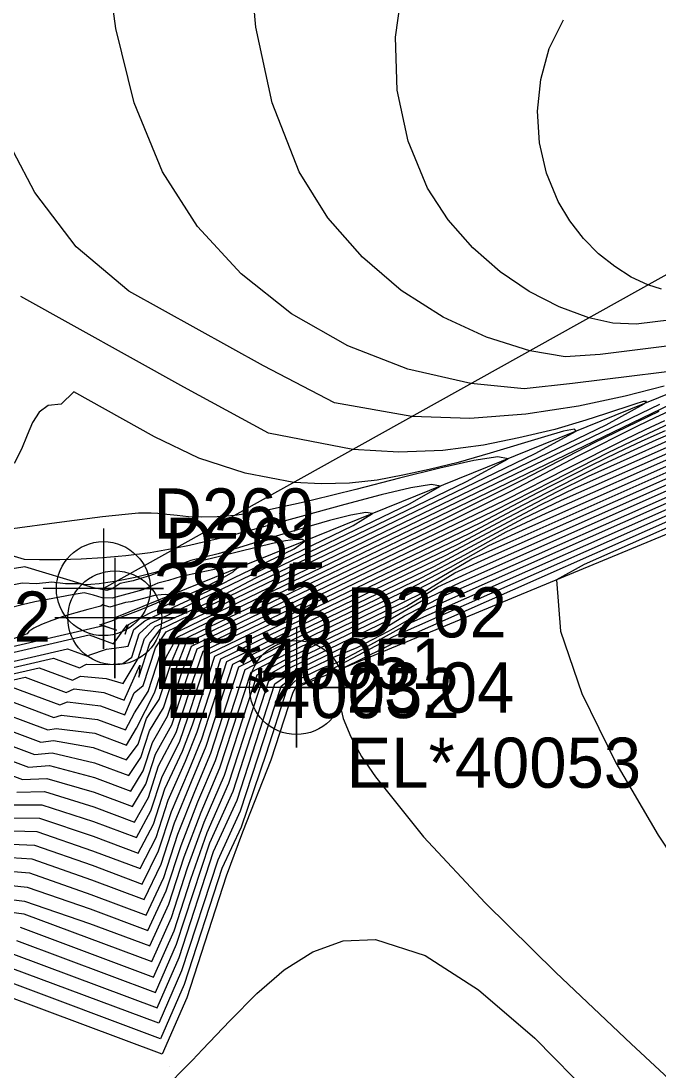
# Model space of a CAD drawing. Extents: x 2356077 to 2359823, y 225951 to 227822.
# Drawn here: x 2356615.2 to 2356647.1, y 227137.3 to 227189.6 of the extents above; entities that cross this region are included whole.
import ezdxf

# ---------------------------------------------------------------- set-up
doc = ezdxf.new("R2010")
doc.units = 0
for name, color, linetype in [('DTM Contours Major', 7, 'Continuous'), ('DTM Contours Minor', 7, 'Continuous'), ('Exist DTM Breakline', 7, 'Continuous'), ('Exist DTM Breakline Cogo Comment', 7, 'Continuous'), ('Exist DTM Breakline Cogo Elevation', 7, 'Continuous'), ('Exist DTM Breakline Cogo Number', 7, 'Continuous'), ('Exist DTM Breakline Cogo Point CELL', 7, 'Continuous'), ('PH Exist DTM Point', 7, 'Continuous')]:
    doc.layers.add(name, color=color, linetype=linetype)

msp = doc.modelspace()

# ---------------------------------------------------------------- linework, layer by layer
at = {"layer": 'DTM Contours Major'}
for points in [[(2356650.01, 227172.448), (2356642.738, 227171.549), (2356640.339, 227171.28), (2356637.674, 227171.536), (2356634.535, 227172.259), (2356631.531, 227173.429), (2356628.734, 227175.021), (2356626.215, 227177.013), (2356624.045, 227179.379), (2356622.295, 227182.097), (2356620.877, 227185.54), (2356619.972, 227189.251), (2356619.463, 227193.083)], [(2356615.023, 227143.755), (2356621.944, 227141.169), (2356622.999, 227143.575), (2356624.65, 227148.638), (2356625.814, 227151.21), (2356627.607, 227156.72), (2356628.683, 227157.379), (2356633.573, 227159.741), (2356635.194, 227160.69), (2356637.173, 227161.639), (2356649.972, 227167.313), (2356650.439, 227167.465), (2356651.114, 227167.675), (2356652.444, 227168.073), (2356653.739, 227168.444), (2356655.677, 227168.977), (2356656.136, 227169.085), (2356661.39, 227170.295), (2356670.074, 227172.299), (2356673.007, 227172.997), (2356680.252, 227175.044)], [(2356678.093, 227172.544), (2356655.561, 227167.344), (2356655.084, 227167.243), (2356654.826, 227167.194), (2356654.557, 227167.153), (2356654.09, 227166.995), (2356653.759, 227166.903), (2356652.029, 227166.502), (2356650.908, 227166.251), (2356650.707, 227166.131), (2356650.549, 227166.024), (2356634.344, 227158.84), (2356631.306, 227157.344), (2356631.098, 227156.541), (2356631.103, 227155.705), (2356631.304, 227154.831), (2356631.684, 227153.913), (2356632.227, 227152.943), (2356632.915, 227151.918), (2356635.318, 227148.938), (2356638.393, 227145.645), (2356641.918, 227142.16), (2356645.672, 227138.604), (2356649.432, 227135.1)], [(2356612.679, 227154.982), (2356616.238, 227153.652), (2356616.87, 227153.732), (2356618.841, 227153.387), (2356620.503, 227152.766), (2356621.082, 227153.556), (2356621.497, 227154.831), (2356622.136, 227155.779), (2356622.744, 227157.647), (2356623.193, 227158.705), (2356650.047, 227171.678)], [(2356614.748, 227150.522), (2356616.285, 227150.532), (2356618.86, 227149.694), (2356620.997, 227148.895), (2356621.719, 227150.223), (2356622.263, 227151.895), (2356623.161, 227153.703), (2356623.563, 227154.875), (2356624.079, 227156.459), (2356624.612, 227158.064), (2356638.204, 227164.63), (2356641.014, 227166.101), (2356643.681, 227167.465), (2356644.993, 227168.104), (2356646.222, 227168.682), (2356647.377, 227169.203)], [(2356613.461, 227147.317), (2356615.666, 227147.141), (2356618.725, 227146.058), (2356621.475, 227145.03), (2356622.36, 227146.9), (2356623.064, 227149.066), (2356623.906, 227151.189), (2356624.707, 227153.1), (2356626.112, 227157.418), (2356628.369, 227158.553), (2356635.23, 227161.868), (2356637.37, 227163.004), (2356639.43, 227164.146), (2356641.427, 227165.07), (2356648.56, 227168.232)], [(2356612.588, 227156.551), (2356616.155, 227157.369), (2356617.818, 227156.748), (2356618.207, 227156.938), (2356619.49, 227156.831), (2356620.343, 227156.575), (2356621.082, 227157.832), (2356621.404, 227158.82), (2356621.926, 227159.419), (2356624.84, 227160.735), (2356626.951, 227161.847), (2356634.606, 227165.545), (2356636.157, 227166.422), (2356635.718, 227166.507), (2356634.686, 227166.345), (2356633.196, 227165.994), (2356631.383, 227165.512), (2356627.329, 227164.392), (2356625.806, 227163.986), (2356625.066, 227163.799), (2356624.344, 227163.624), (2356623.64, 227163.465), (2356622.957, 227163.324), (2356621.675, 227163.101), (2356620.468, 227162.944), (2356619.325, 227162.841), (2356618.234, 227162.78), (2356617.184, 227162.752), (2356616.163, 227162.743), (2356615.412, 227162.757), (2356613.57, 227163.308)]]:
    msp.add_lwpolyline(points, dxfattribs=at)
at = {"layer": 'DTM Contours Minor'}
for points in [[(2356650.746, 227173.818), (2356644.113, 227172.997), (2356642.382, 227172.871), (2356640.617, 227173.179), (2356638.45, 227173.85), (2356636.287, 227174.854), (2356634.201, 227176.186), (2356632.263, 227177.841), (2356630.544, 227179.814), (2356629.115, 227182.1), (2356627.758, 227185.545), (2356626.949, 227189.324), (2356626.609, 227193.239)], [(2356651.2, 227175.152), (2356645.918, 227174.499), (2356644.746, 227174.546), (2356643.56, 227174.821), (2356642.083, 227175.362), (2356640.589, 227176.13), (2356639.132, 227177.116), (2356637.765, 227178.31), (2356636.542, 227179.704), (2356635.517, 227181.288), (2356634.541, 227183.63), (2356634.005, 227186.176), (2356633.915, 227188.817), (2356634.278, 227191.444)], [(2356647.179, 227176.242), (2356646.503, 227176.464), (2356645.675, 227176.854), (2356644.845, 227177.375), (2356644.04, 227178.02), (2356643.285, 227178.781), (2356642.605, 227179.651), (2356642.025, 227180.621), (2356641.449, 227182.033), (2356641.104, 227183.554), (2356641.003, 227185.132), (2356641.158, 227186.715), (2356641.582, 227188.252), (2356642.29, 227189.691)], [(2356647.309, 227171.404), (2356645.367, 227170.904), (2356643.037, 227170.406), (2356640.42, 227170.008), (2356637.617, 227169.805), (2356634.73, 227169.894), (2356630.881, 227170.584), (2356627.328, 227172.433), (2356620.626, 227176.156), (2356617.986, 227178.361), (2356615.934, 227181.068), (2356614.844, 227183.13)], [(2356612.706, 227145.45), (2356615.389, 227145.093), (2356621.766, 227142.71), (2356622.745, 227144.909), (2356623.549, 227147.38), (2356624.382, 227149.665), (2356625.382, 227152), (2356627.012, 227157.009), (2356628.556, 227157.848), (2356633.396, 227160.186), (2356635.255, 227161.105), (2356636.869, 227162.097), (2356638.918, 227163.03), (2356649.686, 227167.804), (2356650.547, 227168.087), (2356651.717, 227168.458), (2356652.869, 227168.806), (2356654.199, 227169.19), (2356655.566, 227169.57), (2356656.236, 227169.749), (2356668.347, 227172.543), (2356670.934, 227173.167), (2356679.732, 227175.653)], [(2356614.059, 227155.941), (2356616.874, 227154.889), (2356617.264, 227155.004), (2356619.059, 227154.78), (2356620.449, 227154.261), (2356620.901, 227155.116), (2356621.58, 227156.188), (2356622.213, 227158.132), (2356622.755, 227159.024), (2356644.417, 227169.489), (2356646.31, 227170.53), (2356646.433, 227170.654), (2356646.269, 227170.641), (2356645.851, 227170.517), (2356644.388, 227170.027), (2356643.408, 227169.708), (2356641.859, 227169.256), (2356640.059, 227168.836), (2356638.3, 227168.46), (2356636.269, 227168.207), (2356634.087, 227168.122), (2356631.787, 227168.251), (2356627.585, 227169.066), (2356623.358, 227171.361), (2356615.232, 227175.876)], [(2356615.208, 227144.423), (2356621.856, 227141.939), (2356622.872, 227144.242), (2356623.709, 227146.814), (2356624.519, 227149.152), (2356625.601, 227151.614), (2356627.31, 227156.867), (2356628.619, 227157.613), (2356634.47, 227160.439), (2356636.028, 227161.4), (2356638.05, 227162.337), (2356649.819, 227167.554), (2356651.123, 227167.97), (2356652.366, 227168.349), (2356653.632, 227168.717), (2356654.95, 227169.087), (2356655.626, 227169.272), (2356656.207, 227169.422), (2356669.203, 227172.42), (2356671.967, 227173.081), (2356680.063, 227175.368)], [(2356614.868, 227143.076), (2356622.032, 227140.399), (2356623.127, 227142.908), (2356624.847, 227148.194), (2356626.014, 227150.766), (2356627.902, 227156.568), (2356628.748, 227157.145), (2356631.525, 227158.486), (2356632.933, 227159.081), (2356634.367, 227159.954), (2356636.294, 227160.94), (2356650.1, 227167.061), (2356650.393, 227167.165), (2356651.114, 227167.385), (2356652.537, 227167.803), (2356653.857, 227168.175), (2356655.096, 227168.514), (2356655.631, 227168.649), (2356656.369, 227168.815), (2356670.939, 227172.178), (2356674.04, 227172.911), (2356680.422, 227174.714)], [(2356680.521, 227174.363), (2356675.065, 227172.822), (2356671.803, 227172.056), (2356656.211, 227168.458), (2356655.553, 227168.313), (2356655.122, 227168.214), (2356654.576, 227168.073), (2356652.646, 227167.543), (2356651.887, 227167.327), (2356651.125, 227167.105), (2356650.408, 227166.888), (2356650.29, 227166.829), (2356650.219, 227166.804), (2356635.418, 227160.243), (2356633.542, 227159.175), (2356631.986, 227158.354), (2356630.892, 227157.915), (2356628.813, 227156.911), (2356628.195, 227156.411), (2356626.178, 227150.214), (2356625.052, 227147.769), (2356623.253, 227142.239), (2356622.118, 227139.629), (2356614.702, 227142.401)], [(2356678.704, 227172.364), (2356654.663, 227166.815), (2356654.556, 227166.801), (2356654.458, 227166.798), (2356654.374, 227166.815), (2356654.131, 227166.69), (2356653.89, 227166.624), (2356652.783, 227166.365), (2356651.253, 227166.013), (2356650.921, 227165.88), (2356643.322, 227162.511), (2356641.94, 227161.75), (2356642.15, 227159.196), (2356643.204, 227156.086), (2356644.896, 227152.624), (2356647.018, 227149.017), (2356649.365, 227145.471), (2356651.729, 227142.191), (2356653.059, 227140.45), (2356654.329, 227138.852), (2356655.548, 227137.372), (2356656.722, 227135.988)], [(2356614.756, 227156.417), (2356617.177, 227155.512), (2356617.561, 227155.665), (2356619.21, 227155.461), (2356620.415, 227155.011), (2356620.881, 227156.112), (2356621.33, 227156.477), (2356621.943, 227158.362), (2356622.479, 227159.156), (2356640.884, 227168.047), (2356642.926, 227169.161), (2356642.843, 227169.265), (2356642.291, 227169.158), (2356641.352, 227168.889), (2356638.644, 227168.062), (2356637.038, 227167.603), (2356635.587, 227167.258), (2356634.286, 227166.969), (2356633.002, 227166.73), (2356631.619, 227166.579), (2356630.23, 227166.531), (2356628.844, 227166.609), (2356626.427, 227167.068), (2356624.11, 227167.818), (2356621.906, 227168.89), (2356617.881, 227171.126), (2356617.247, 227170.521), (2356616.598, 227170.44), (2356616.146, 227170.114), (2356615.821, 227169.603), (2356615.551, 227168.967), (2356615.267, 227168.266), (2356614.896, 227167.558)], [(2356613.361, 227155.464), (2356616.574, 227154.263), (2356616.988, 227154.334), (2356618.923, 227154.094), (2356620.496, 227153.506), (2356620.997, 227154.352), (2356621.898, 227156.107), (2356622.482, 227157.9), (2356623.029, 227158.891), (2356647.104, 227170.521)], [(2356611.299, 227154.023), (2356615.613, 227152.411), (2356616.669, 227152.487), (2356618.907, 227151.888), (2356620.711, 227151.214), (2356621.337, 227152.224), (2356621.796, 227153.634), (2356622.553, 227154.945), (2356623.278, 227157.171), (2356623.746, 227158.442), (2356636.096, 227164.408), (2356639.692, 227166.183), (2356643.017, 227167.941), (2356646.007, 227169.436), (2356646.892, 227169.858), (2356647.727, 227170.246)], [(2356611.99, 227154.502), (2356615.919, 227153.034), (2356616.79, 227153.12), (2356618.9, 227152.627), (2356620.611, 227151.988), (2356621.21, 227152.89), (2356621.642, 227154.22), (2356622.348, 227155.371), (2356623.01, 227157.408), (2356623.461, 227158.57), (2356636.479, 227164.858), (2356640.275, 227166.751), (2356643.845, 227168.599), (2356647.067, 227170.165)], [(2356610.608, 227153.544), (2356615.313, 227151.786), (2356616.535, 227151.844), (2356618.895, 227151.155), (2356620.806, 227150.441), (2356621.465, 227151.556), (2356621.951, 227153.05), (2356622.759, 227154.52), (2356623.545, 227156.935), (2356624.033, 227158.315), (2356639.408, 227165.743), (2356642.482, 227167.301), (2356645.35, 227168.747), (2356646.382, 227169.247), (2356647.346, 227169.702)], [(2356614.479, 227149.886), (2356616.161, 227149.865), (2356618.837, 227148.965), (2356621.092, 227148.122), (2356621.847, 227149.558), (2356622.422, 227151.324), (2356623.3, 227153.201), (2356623.793, 227154.524), (2356624.905, 227157.939), (2356637.614, 227164.08), (2356640.282, 227165.486), (2356642.841, 227166.809), (2356644.277, 227167.515), (2356645.632, 227168.153), (2356646.909, 227168.728), (2356648.115, 227169.245)], [(2356615.026, 227151.156), (2356616.409, 227151.192), (2356618.879, 227150.424), (2356620.902, 227149.668), (2356621.592, 227150.889), (2356622.106, 227152.469), (2356622.977, 227154.13), (2356623.812, 227156.697), (2356624.321, 227158.189), (2356638.817, 227165.192), (2356641.759, 227166.695), (2356644.527, 227168.1), (2356645.704, 227168.672), (2356646.803, 227169.19), (2356647.831, 227169.658)], [(2356614.217, 227149.247), (2356616.037, 227149.192), (2356618.811, 227148.237), (2356621.188, 227147.349), (2356621.975, 227148.893), (2356622.582, 227150.757), (2356623.445, 227152.698), (2356624.023, 227154.17), (2356625.207, 227157.811), (2356628.185, 227159.26), (2356637.022, 227163.529), (2356639.55, 227164.869), (2356641.994, 227166.15), (2356643.547, 227166.919), (2356645.136, 227167.641), (2356647.814, 227168.828)], [(2356613.711, 227147.961), (2356615.79, 227147.828), (2356618.755, 227146.784), (2356621.379, 227145.803), (2356622.231, 227147.564), (2356622.903, 227149.628), (2356623.749, 227151.691), (2356624.48, 227153.459), (2356625.811, 227157.55), (2356628.307, 227158.788), (2356635.831, 227162.423), (2356638.092, 227163.628), (2356640.286, 227164.818), (2356642.193, 227165.718), (2356648.655, 227168.583)], [(2356613.962, 227148.605), (2356615.913, 227148.513), (2356618.784, 227147.51), (2356621.284, 227146.576), (2356622.103, 227148.228), (2356622.742, 227150.192), (2356623.595, 227152.195), (2356624.252, 227153.816), (2356625.509, 227157.681), (2356628.245, 227159.024), (2356636.428, 227162.977), (2356641.142, 227165.485), (2356642.884, 227166.333), (2356647.581, 227168.416)], [(2356612.013, 227156.115), (2356615.454, 227156.894), (2356617.492, 227156.132), (2356617.899, 227156.311), (2356619.377, 227156.136), (2356620.394, 227155.756), (2356621.163, 227157.502), (2356621.12, 227156.89), (2356621.673, 227158.589), (2356622.184, 227159.279), (2356637.461, 227166.659), (2356639.541, 227167.791), (2356639.012, 227167.883), (2356637.816, 227167.702), (2356636.124, 227167.323), (2356634.107, 227166.818), (2356631.937, 227166.262), (2356629.784, 227165.728), (2356629.058, 227165.558), (2356628.359, 227165.403), (2356627.691, 227165.263), (2356627.056, 227165.143), (2356626.458, 227165.043), (2356625.9, 227164.966), (2356625.019, 227164.889), (2356624.257, 227164.874), (2356623.597, 227164.901), (2356623.022, 227164.952), (2356622.515, 227165.011), (2356622.059, 227165.058), (2356621.732, 227165.077), (2356621.414, 227165.08), (2356621.098, 227165.069), (2356620.772, 227165.047), (2356620.428, 227165.014), (2356619.313, 227164.886), (2356617.531, 227164.661), (2356614.319, 227164.234)], [(2356612.971, 227146.026), (2356615.419, 227145.718), (2356618.652, 227144.611), (2356621.662, 227143.486), (2356622.616, 227145.57), (2356623.386, 227147.939), (2356624.225, 227150.16), (2356625.159, 227152.371), (2356626.713, 227157.148), (2356628.493, 227158.083), (2356634.015, 227160.75), (2356635.951, 227161.748), (2356637.72, 227162.791), (2356639.777, 227163.72), (2356649.508, 227168.034)], [(2356613.223, 227146.669), (2356615.546, 227146.426), (2356618.689, 227145.334), (2356621.569, 227144.258), (2356622.488, 227146.235), (2356623.225, 227148.502), (2356624.067, 227150.674), (2356624.934, 227152.738), (2356626.413, 227157.284), (2356628.431, 227158.318), (2356634.625, 227161.31), (2356636.656, 227162.378), (2356638.573, 227163.471), (2356640.616, 227164.401), (2356648.446, 227167.872)], [(2356650.53, 227166.326), (2356633.803, 227158.909), (2356630.274, 227157.048), (2356629.933, 227156.88), (2356629.417, 227156.612), (2356629.16, 227156.548), (2356628.955, 227156.449), (2356628.793, 227156.132), (2356627.692, 227152.75), (2356626.291, 227149.163), (2356625.479, 227146.965), (2356623.506, 227140.899), (2356622.279, 227138.095), (2356614.362, 227141.053)], [(2356650.33, 227166.545), (2356634.559, 227159.553), (2356631.889, 227158.073), (2356630.989, 227157.617), (2356630.254, 227157.342), (2356628.881, 227156.679), (2356628.488, 227156.253), (2356627.461, 227153.096), (2356626.225, 227149.417), (2356625.263, 227147.357), (2356623.38, 227141.569), (2356622.201, 227138.861), (2356614.537, 227141.725)], [(2356595.171, 227152.821), (2356616.86, 227157.843), (2356618.162, 227157.356), (2356618.512, 227157.538), (2356619.594, 227157.529), (2356620.323, 227157.572), (2356620.761, 227157.901), (2356621.135, 227159.052), (2356621.692, 227159.572), (2356631.8, 227164.455), (2356632.773, 227165.052), (2356632.436, 227165.101), (2356631.693, 227164.975), (2356630.626, 227164.708), (2356629.317, 227164.335), (2356627.847, 227163.89), (2356626.298, 227163.409), (2356625.068, 227163.05), (2356623.705, 227162.711), (2356622.843, 227162.404), (2356621.928, 227162.109), (2356620.937, 227161.868), (2356620.014, 227161.682), (2356619.565, 227161.611), (2356619.134, 227161.556), (2356618.72, 227161.516), (2356618.409, 227161.501), (2356615.425, 227162.392), (2356614.309, 227162.222)], [(2356598.231, 227153.833), (2356617.56, 227158.31), (2356617.93, 227158.18), (2356618.556, 227157.946), (2356618.682, 227158.016), (2356619.51, 227158.297), (2356620.245, 227158.389), (2356620.592, 227158.44), (2356620.865, 227159.279), (2356621.413, 227159.702), (2356622.879, 227160.411), (2356624.555, 227161.185), (2356625.854, 227161.848), (2356628.864, 227163.302), (2356629.388, 227163.682), (2356629.265, 227163.77), (2356628.931, 227163.769), (2356628.423, 227163.694), (2356627.776, 227163.561), (2356627.028, 227163.386), (2356624.129, 227162.663), (2356623.42, 227162.494), (2356622.707, 227162.331), (2356621.649, 227161.955), (2356621.206, 227161.813), (2356620.832, 227161.707), (2356620.498, 227161.626), (2356620.185, 227161.564), (2356619.781, 227161.295), (2356619.522, 227161.225), (2356618.849, 227161.355), (2356618.184, 227161.554), (2356617.462, 227161.547), (2356616.781, 227161.626), (2356616.022, 227161.547), (2356615.297, 227161.583), (2356613.054, 227161.143)], [(2356618.635, 227159.008), (2356619.847, 227158.555), (2356620.532, 227159.505), (2356620.444, 227159.045), (2356620.602, 227159.53), (2356621.648, 227160.081), (2356623.408, 227160.931), (2356624.503, 227161.441), (2356625.279, 227161.835), (2356625.822, 227162.143), (2356626.004, 227162.313), (2356626.009, 227162.374), (2356625.939, 227162.404), (2356625.802, 227162.408), (2356625.605, 227162.39), (2356625.356, 227162.352), (2356624.804, 227162.248), (2356623.229, 227161.923), (2356622.597, 227161.719), (2356622.06, 227161.583), (2356621.314, 227161.258), (2356619.787, 227160.844), (2356619.297, 227160.86), (2356618.865, 227160.989), (2356618.385, 227161.098), (2356617.791, 227161.001), (2356617.184, 227160.894), (2356616.562, 227160.776), (2356615.936, 227160.647), (2356615.298, 227160.502), (2356614.647, 227160.343)], [(2356619.351, 227159.477), (2356619.997, 227159.236), (2356619.177, 227159.511), (2356619.47, 227159.614), (2356619.775, 227159.704), (2356620.035, 227159.817), (2356620.565, 227160.014), (2356621.106, 227160.221), (2356621.584, 227160.413), (2356621.986, 227160.586), (2356622.3, 227160.734), (2356622.515, 227160.855), (2356622.62, 227160.943), (2356622.602, 227160.998), (2356622.469, 227161.017), (2356622.236, 227161.007), (2356621.92, 227160.97), (2356620.726, 227160.647), (2356620.446, 227160.616), (2356619.668, 227160.389), (2356619.309, 227160.496), (2356619.216, 227160.439), (2356618.582, 227160.279), (2356617.968, 227160.11), (2356617.39, 227159.934), (2356616.784, 227159.727), (2356616.271, 227159.525), (2356615.876, 227159.339), (2356615.625, 227159.178), (2356615.543, 227159.052), (2356611.984, 227157.771), (2356619.351, 227159.477)], [(2356602.024, 227155.161), (2356618.635, 227159.008)], [(2356622.742, 227136.731), (2356623.268, 227137.26), (2356623.786, 227137.793), (2356624.298, 227138.329), (2356625.647, 227139.756), (2356626.996, 227141.109), (2356628.371, 227142.29), (2356629.8, 227143.2), (2356631.308, 227143.739), (2356632.924, 227143.81), (2356635.391, 227143.012), (2356638.058, 227141.304), (2356640.862, 227138.887), (2356643.741, 227135.962)]]:
    msp.add_lwpolyline(points, dxfattribs=at)
at = {"layer": 'Exist DTM Breakline'}
for points in [[(2356732.647, 227097.121), (2356737.418, 227142.921), (2356719.914, 227162.219), (2356687.802, 227185.182), (2356650.898, 227178.916), (2356619.351, 227161.311)], [(2356711.144, 227157.233), (2356685.837, 227180.995), (2356651.307, 227172.553), (2356619.923, 227159.851)], [(2356710.017, 227151.057), (2356683.364, 227172.218), (2356651.181, 227165.578), (2356628.977, 227156.38)]]:
    msp.add_lwpolyline(points, dxfattribs=at)
at = {"layer": 'Exist DTM Breakline Cogo Point CELL'}
for points in [[(2356619.351, 227164.311), (2356619.351, 227158.311), (2356619.351, 227161.311), (2356622.351, 227161.311), (2356616.351, 227161.311)], [(2356619.923, 227162.851), (2356619.923, 227156.851), (2356619.923, 227159.851), (2356622.923, 227159.851), (2356616.923, 227159.851)], [(2356628.977, 227159.38), (2356628.977, 227153.38), (2356628.977, 227156.38), (2356631.977, 227156.38), (2356625.977, 227156.38)]]:
    msp.add_lwpolyline(points, dxfattribs=at)
for centre in [(2356619.351, 227161.311), (2356619.923, 227159.851), (2356628.977, 227156.38)]:
    msp.add_circle(centre, 2.344, dxfattribs=at)
at = {"layer": 'PH Exist DTM Point'}
msp.add_line((2356622.624, 227137.453), (2356622.624, 227137.453), dxfattribs=at)

# ---------------------------------------------------------------- texts
at = {"layer": 'Exist DTM Breakline Cogo Comment'}
for s, p in [('EL*40052', (2356602.046, 227158.669)), ('EL*40051', (2356621.851, 227156.312)), ('EL*40052', (2356622.423, 227154.852)), ('EL*40053', (2356631.477, 227151.38))]:
    msp.add_text(s, height=2.5, dxfattribs=at).set_placement(p)
at = {"layer": 'Exist DTM Breakline Cogo Elevation'}
for s, p in [('28.25', (2356621.851, 227160.062)), ('28.96', (2356622.423, 227158.602)), ('23.04', (2356631.477, 227155.13))]:
    msp.add_text(s, height=2.5, dxfattribs=at).set_placement(p)
at = {"layer": 'Exist DTM Breakline Cogo Number'}
for s, p in [('D260', (2356621.851, 227163.812)), ('D261', (2356622.423, 227162.352)), ('D262', (2356631.477, 227158.88))]:
    msp.add_text(s, height=2.5, dxfattribs=at).set_placement(p)

doc.saveas('drawing.dxf')
